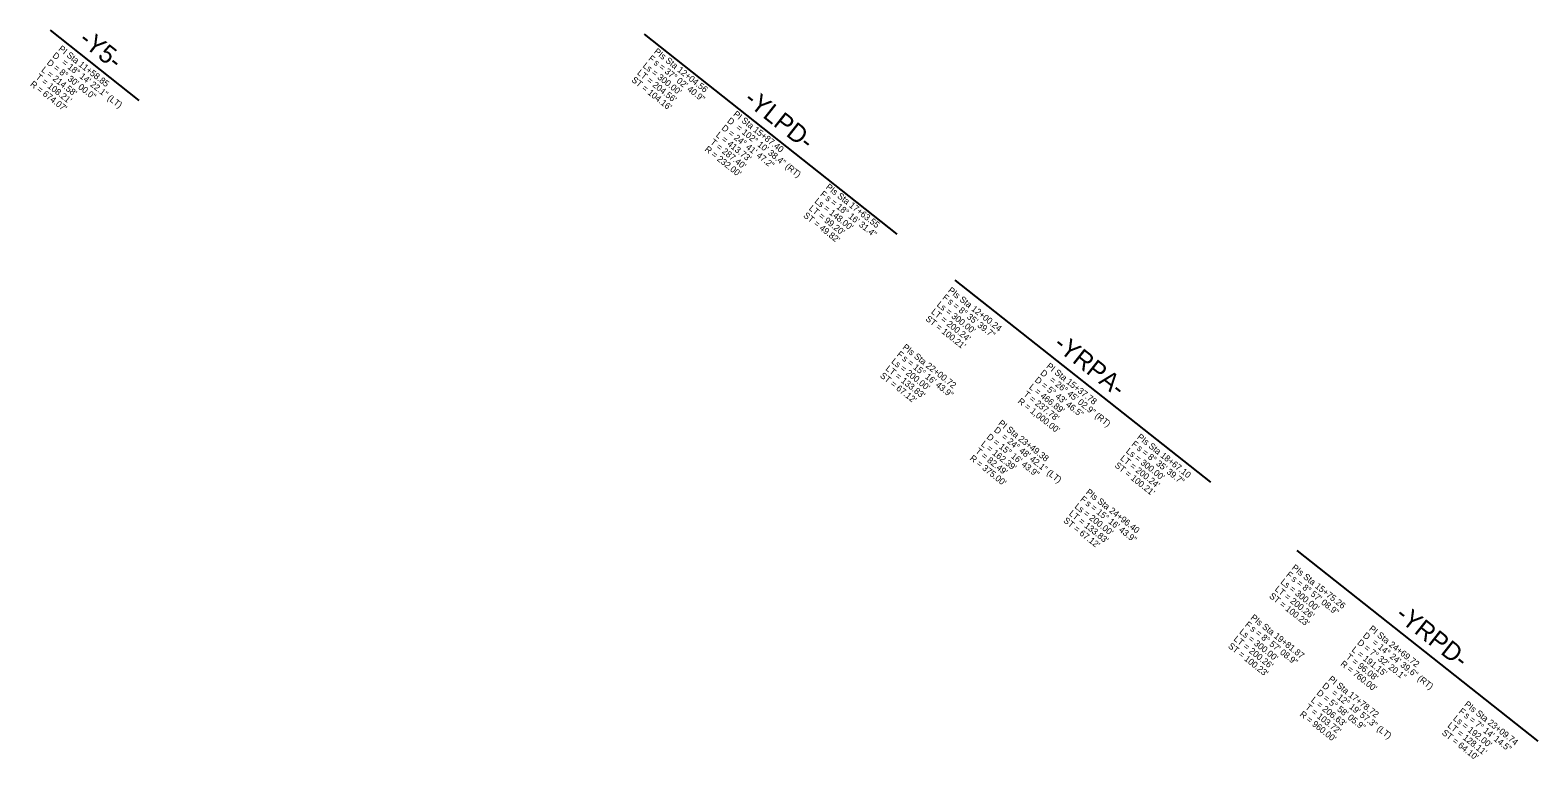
# Model space of a CAD drawing. Extents: x 1778969 to 1790720, y 807089 to 817794.
# Drawn here: x 1784900 to 1786563, y 813423 to 814227 of the extents above; entities that cross this region are included whole.
import ezdxf

# ---------------------------------------------------------------- set-up
doc = ezdxf.new("R2010")
doc.units = 0
doc.layers.add('Prop Horizontal Alignment Curve and Spiral Data', color=7, linetype='Continuous')
doc.layers.add('Prop Horizontal Alignment Station Label', color=7, linetype='Continuous')

msp = doc.modelspace()

# ---------------------------------------------------------------- linework, layer by layer
at = {"layer": 'Prop Horizontal Alignment Station Label'}
for p, q in [((1784922.3, 814226.9), (1785020.3, 814149.3)), ((1785577.6, 814222.5), (1785856.4, 814001.8)), ((1785920.4, 813951.2), (1786202.1, 813728.2)), ((1786297.5, 813652.6), (1786563.3, 813442.2))]:
    msp.add_line(p, q, dxfattribs=at)

# ---------------------------------------------------------------- texts
at = {"layer": 'Prop Horizontal Alignment Curve and Spiral Data'}
for s, rotation, p in [('D', 322.1411, (1784924.3, 814197.7)), ('PI Sta 11+58.85', 322.1411, (1784930.9, 814205.1)), ('F', 321.6948, (1785581.6, 814194.4)), ('PIs Sta 12+04.56', 321.6948, (1785587.8, 814202.2)), ("L = 214.58'", 322.1411, (1784912, 814181.9)), ('D = 8%%d 30\' 00.0"', 322.1411, (1784918.1, 814189.8)), ('= 18%%d 14\' 22.1" (LT)', 322.1411, (1784934.6, 814190)), ("LT = 204.56'", 321.6948, (1785569.2, 814178.7)), ("Ls = 300.00'", 321.6948, (1785575.4, 814186.5)), ('s = 37%%d 02\' 40.9"', 321.6948, (1785587.5, 814189.7)), ("R = 674.07'", 322.1411, (1784899.7, 814166.1)), ("T = 108.21'", 322.1411, (1784905.9, 814174)), ("ST = 104.16'", 321.6948, (1785563, 814170.8)), ('PI Sta 15+87.40', 321.6948, (1785675.2, 814133.1)), ('D = 24%%d 41\' 47.2"', 321.6948, (1785662.3, 814117.8)), ('D', 321.6948, (1785668.5, 814125.7)), ('= 102%%d 10\' 38.4" (RT)', 321.6948, (1785678.3, 814118.1)), ("R = 232.00'", 321.6948, (1785643.7, 814094.3)), ("T = 287.40'", 321.6948, (1785649.9, 814102.1)), ("L = 413.73'", 321.6948, (1785656.1, 814110)), ('F', 321.6948, (1785771.1, 814044.8)), ('PIs Sta 17+63.55', 321.6948, (1785777.3, 814052.7)), ("LT = 99.20'", 321.6948, (1785758.7, 814029.1)), ("Ls = 148.00'", 321.6948, (1785764.9, 814037)), ('s = 18%%d 16\' 31.4"', 321.6948, (1785777, 814040.2)), ("ST = 49.82'", 321.6948, (1785752.5, 814021.3)), ('F', 321.6243, (1785905.9, 813930.7)), ('PIs Sta 12+00.24', 321.6243, (1785912.1, 813938.6)), ("LT = 200.24'", 321.6243, (1785893.5, 813915)), ("Ls = 300.00'", 321.6243, (1785899.7, 813922.9)), ('s = 8%%d 35\' 39.7"', 321.6243, (1785911.8, 813926.1)), ("ST = 100.21'", 321.6243, (1785887.3, 813907.2)), ('F', 321.6243, (1785855.7, 813868)), ('s = 15%%d 16\' 43.9"', 321.6243, (1785861.6, 813863.3)), ('PIs Sta 22+00.72', 321.6243, (1785861.9, 813875.8)), ("LT = 133.83'", 321.6243, (1785843.3, 813852.3)), ("Ls = 200.00'", 321.6243, (1785849.5, 813860.2)), ('D', 321.6243, (1786013.9, 813847.5)), ('PI Sta 15+37.78', 321.6243, (1786020.6, 813855)), ("ST = 67.12'", 321.6243, (1785837.1, 813844.5)), ("L = 466.89'", 321.6243, (1786001.5, 813831.9)), ('D = 5%%d 43\' 46.5"', 321.6243, (1786007.7, 813839.7)), ('= 26%%d 45\' 02.9" (RT)', 321.6243, (1786024.1, 813839.8)), ("R = 1,000.00'", 321.6243, (1785989, 813816.2)), ("T = 237.78'", 321.6243, (1785995.3, 813824)), ('D', 321.4648, (1785962.8, 813784.6)), ('PI Sta 23+49.38', 321.6243, (1785967.6, 813792.1)), ("T = 82.49'", 321.6243, (1785942.3, 813761.2)), ("L = 162.39'", 321.6243, (1785948.5, 813769)), ('D = 15%%d 16\' 43.9"', 321.6243, (1785954.7, 813776.9)), ('= 24%%d 48\' 42.1" (LT)', 321.6243, (1785971.1, 813777)), ("Ls = 300.00'", 321.6243, (1786108.3, 813761.2)), ('F', 321.6243, (1786114.5, 813769)), ('s = 8%%d 35\' 39.7"', 321.6243, (1786120.4, 813764.3)), ('PIs Sta 18+67.10', 321.6243, (1786120.7, 813776.8)), ("R = 375.00'", 321.6243, (1785936.1, 813753.3)), ("ST = 100.21'", 321.6243, (1786095.9, 813745.5)), ("LT = 200.24'", 321.6243, (1786102.1, 813753.3)), ('PIs Sta 24+96.40', 321.6243, (1786064.1, 813715.9)), ("Ls = 200.00'", 321.6243, (1786051.7, 813700.2)), ('F', 321.6243, (1786057.9, 813708.1)), ('s = 15%%d 16\' 43.9"', 321.6243, (1786063.8, 813703.4)), ("ST = 67.12'", 321.6243, (1786039.3, 813684.6)), ("LT = 133.83'", 321.6243, (1786045.5, 813692.4)), ('PIs Sta 15+75.26', 321.6309, (1786291.2, 813632.6)), ("Ls = 300.00'", 321.6309, (1786278.8, 813616.9)), ('F', 321.6309, (1786285, 813624.8)), ('s = 8%%d 57\' 08.9"', 321.6309, (1786290.9, 813620.1)), ("ST = 100.23'", 321.6309, (1786266.4, 813601.3)), ("LT = 200.26'", 321.6309, (1786272.6, 813609.1)), ("Ls = 300.00'", 321.6309, (1786233.4, 813561.8)), ('F', 321.6309, (1786239.6, 813569.7)), ('s = 8%%d 57\' 08.9"', 321.6309, (1786245.5, 813565)), ('PIs Sta 19+81.87', 321.6309, (1786245.8, 813577.5)), ('PI Sta 24+69.72', 321.6309, (1786376.4, 813565.2)), ("ST = 100.23'", 321.6309, (1786221, 813546.1)), ("LT = 200.26'", 321.6309, (1786227.2, 813554)), ('D = 7%%d 32\' 20.1"', 321.6309, (1786363.5, 813549.9)), ('D', 321.6309, (1786369.7, 813557.7)), ('= 14%%d 24\' 39.6" (RT)', 321.6309, (1786379.9, 813550)), ("T = 96.08'", 321.6309, (1786351.1, 813534.2)), ("L = 191.15'", 321.6309, (1786357.3, 813542.1)), ("R = 760.00'", 321.6309, (1786344.9, 813526.4)), ('D', 321.6309, (1786324.8, 813502.2)), ('PI Sta 17+78.72', 321.6309, (1786331.6, 813509.6)), ("T = 103.72'", 321.6309, (1786306.2, 813478.7)), ("L = 206.63'", 321.6309, (1786312.4, 813486.5)), ('D = 5%%d 58\' 05.9"', 321.6309, (1786318.6, 813494.4)), ('= 12%%d 19\' 57.3" (LT)', 321.6309, (1786335.1, 813494.5)), ('PIs Sta 23+09.74', 321.6309, (1786481.6, 813481.9)), ("R = 960.00'", 321.6309, (1786300, 813470.8)), ("Ls = 192.00'", 321.6309, (1786469.2, 813466.2)), ('F', 321.6309, (1786475.4, 813474.1)), ('s = 7%%d 14\' 14.5"', 321.6309, (1786481.3, 813469.4)), ("ST = 64.10'", 321.6309, (1786456.8, 813450.5)), ("LT = 128.11'", 321.6309, (1786463, 813458.4))]:
    msp.add_text(s, height=7, rotation=rotation, dxfattribs=at).set_placement(p)
at = {"layer": 'Prop Horizontal Alignment Station Label'}
for s, p in [('-Y5-', (1784952.8, 814213.8)), ('-YLPD-', (1785686.4, 814148)), ('-YRPA-', (1786027.8, 813877.7)), ('-YRPD-', (1786404.9, 813579.1))]:
    msp.add_text(s, height=20, rotation=321.6309, dxfattribs=at).set_placement(p)

doc.saveas('drawing.dxf')
